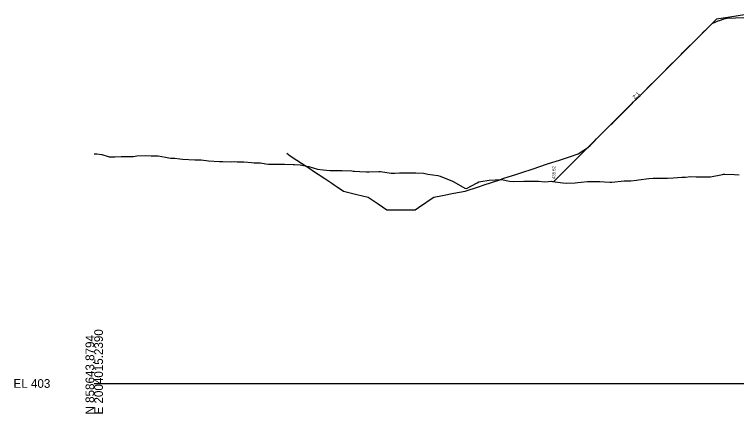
# Model space of a CAD drawing. Extents: x 2004049 to 2067449, y 841632 to 859611.
# Drawn here: x 2060920.8 to 2061153.3, y 856953.8 to 857082.4 of the extents above; entities that cross this region are included whole.
import ezdxf

# ---------------------------------------------------------------- set-up
doc = ezdxf.new("R2010")
doc.units = 0
for name, color, linetype in [('RD_DDB_Profile_Elev', 7, 'Continuous'), ('RD_GPK_XS_Cell', 7, 'Continuous'), ('RD_XS_EarthShd', 7, 'Continuous'), ('RD_XS_EwShp1', 7, 'Continuous'), ('RD_XS_ExGround', 7, 'Continuous'), ('RD_XS_TieSlope', 7, 'Continuous'), ('RD_XS_TX_Ditch', 7, 'Continuous'), ('RD_XS_TX_Slope', 7, 'Continuous')]:
    doc.layers.add(name, color=color, linetype=linetype)

msp = doc.modelspace()

# ---------------------------------------------------------------- linework, layer by layer
at = {"layer": 'RD_DDB_Profile_Elev'}
msp.add_lwpolyline([(2061008.46, 857037.69), (2061009.62, 857036.92), (2061011.71, 857035.53), (2061014.71, 857033.53), (2061015.22, 857033.19), (2061017.72, 857031.53), (2061018.59, 857030.95), (2061020.72, 857029.53), (2061022.95, 857028.04), (2061023.72, 857027.53), (2061024.34, 857027.12), (2061026.72, 857025.53), (2061031.03, 857024.45), (2061034.72, 857023.53), (2061037.92, 857021.39), (2061040.72, 857019.53), (2061044, 857019.53), (2061049.76, 857019.53), (2061051.91, 857020.95), (2061052.77, 857021.53), (2061054, 857022.34), (2061055.78, 857023.53), (2061058.58, 857024.08), (2061062.3, 857024.82), (2061064.09, 857025.17), (2061065.89, 857025.53), (2061070.16, 857026.93), (2061071.97, 857027.53), (2061077.07, 857029.2), (2061078.06, 857029.53), (2061082.53, 857031), (2061084.15, 857031.53), (2061087.44, 857032.61), (2061090.24, 857033.53), (2061090.58, 857033.64), (2061091.48, 857033.94), (2061092.13, 857034.16), (2061092.74, 857034.36), (2061096.27, 857035.53), (2061099.79, 857036.69), (2061102.33, 857037.53), (2061104.09, 857038.7), (2061104.92, 857039.22), (2061105.4, 857039.53), (2061106.1, 857040.22), (2061107.4, 857041.53), (2061108.22, 857042.34), (2061109.4, 857043.53), (2061110.68, 857044.81), (2061111.4, 857045.53), (2061112.84, 857046.96), (2061113.4, 857047.53), (2061115.44, 857049.56), (2061117.4, 857051.53), (2061118.12, 857052.25), (2061119.4, 857053.53), (2061120.14, 857054.27), (2061121.4, 857055.53), (2061122.24, 857056.37), (2061123.4, 857057.53), (2061125.4, 857059.53), (2061126.93, 857061.05), (2061127.4, 857061.53), (2061129.48, 857063.6), (2061131.4, 857065.53), (2061132.16, 857066.28), (2061133.4, 857067.53), (2061135.4, 857069.53), (2061135.89, 857070.02), (2061137.4, 857071.53), (2061139.51, 857073.64), (2061141.4, 857075.53), (2061142.89, 857077.02), (2061143.4, 857077.53), (2061144, 857078.13), (2061145.39, 857079.53), (2061147.31, 857080.33), (2061147.78, 857080.49), (2061149.31, 857081.06), (2061150.21, 857081.21), (2061155.61, 857081.42)], dxfattribs=at)
at = {"layer": 'RD_GPK_XS_Cell'}
msp.add_line((2060946.51, 856963.53), (2061196.51, 856963.53), dxfattribs=at)
at = {"layer": 'RD_XS_EarthShd'}
msp.add_line((2061156.51, 857082.45), (2061150.51, 857081.49), dxfattribs=at)
at = {"layer": 'RD_XS_EwShp1'}
for p, q in [((2061156.51, 857082.45), (2061150.51, 857081.49)), ((2061146.76, 857080.89), (2061094.45, 857028.57)), ((2061150.51, 857081.49), (2061146.76, 857080.89))]:
    msp.add_line(p, q, dxfattribs=at)
at = {"layer": 'RD_XS_ExGround'}
msp.add_lwpolyline([(2060946.51, 857037.57), (2060947.32, 857037.48), (2060949, 857037.34), (2060950.96, 857036.64), (2060951.27, 857036.57), (2060953.12, 857036.59), (2060955.22, 857036.62), (2060955.57, 857036.62), (2060959.17, 857036.68), (2060959.64, 857036.76), (2060960.19, 857036.85), (2060963.11, 857036.99), (2060964.8, 857036.89), (2060966.02, 857036.86), (2060967.06, 857036.89), (2060969.42, 857036.42), (2060971.01, 857036.15), (2060972.41, 857036.14), (2060974.04, 857035.91), (2060974.96, 857035.83), (2060978.91, 857035.62), (2060980.92, 857035.61), (2060983.27, 857035.3), (2060986.81, 857035.06), (2060987.89, 857035.05), (2060990.75, 857035), (2060991.56, 857035.02), (2060992.5, 857034.96), (2060994.7, 857034.91), (2060997.12, 857034.7), (2060997.94, 857034.62), (2060998.65, 857034.64), (2061000.07, 857034.68), (2061001.73, 857034.31), (2061002.6, 857034.21), (2061006.55, 857034.18), (2061007.72, 857034.16), (2061010.5, 857034.07), (2061010.97, 857034.08), (2061012.84, 857033.93), (2061014.44, 857033.7), (2061014.97, 857033.58), (2061015.58, 857033.41), (2061018.39, 857032.6), (2061020.2, 857032.34), (2061022.34, 857032.19), (2061023.48, 857032.15), (2061024.81, 857032.15), (2061026.29, 857032.17), (2061029.43, 857032), (2061029.87, 857031.99), (2061030.24, 857031.95), (2061031.99, 857031.84), (2061034.19, 857031.68), (2061035.01, 857031.72), (2061038.14, 857031.85), (2061038.66, 857031.8), (2061042.08, 857031.35), (2061043.28, 857031.34), (2061044.76, 857031.42), (2061046.03, 857031.38), (2061046.89, 857031.43), (2061047.9, 857031.42), (2061049.98, 857031.39), (2061052.51, 857031.26), (2061053.93, 857031.01), (2061057.13, 857030.51), (2061057.88, 857030.28), (2061061.83, 857028.76), (2061062.31, 857028.5), (2061065.77, 857026.51), (2061066.36, 857026.4), (2061069.72, 857028.16), (2061070.3, 857028.48), (2061070.98, 857028.63), (2061073.67, 857029.01), (2061075.59, 857029.15), (2061077.62, 857029.23), (2061080.21, 857028.74), (2061081.57, 857028.56), (2061084.83, 857028.72), (2061085.52, 857028.68), (2061089.46, 857028.75), (2061091.58, 857028.51), (2061093.71, 857028.68), (2061094.06, 857028.63), (2061097.36, 857028.14), (2061098.67, 857028.09), (2061101.31, 857028.13), (2061102.22, 857028.25), (2061103.29, 857028.43), (2061105.26, 857028.63), (2061107.91, 857028.64), (2061108.61, 857028.63), (2061109.21, 857028.59), (2061110.74, 857028.49), (2061112.52, 857028.4), (2061113.16, 857028.42), (2061117.14, 857028.88), (2061119.25, 857028.79), (2061121.05, 857029.02), (2061121.75, 857029.12), (2061125, 857029.58), (2061126.37, 857029.67), (2061128.95, 857029.65), (2061129.89, 857029.65), (2061130.99, 857029.68), (2061132.9, 857029.75), (2061135.6, 857029.97), (2061136.85, 857030.05), (2061138.4, 857030.18), (2061140.22, 857030.11), (2061140.79, 857030.12), (2061144.2, 857030.15), (2061144.84, 857030.17), (2061148.69, 857030.88), (2061149.04, 857030.93), (2061149.45, 857030.97), (2061152.64, 857030.92), (2061154.07, 857030.72)], dxfattribs=at)
at = {"layer": 'RD_XS_TieSlope'}
for p, q in [((2061146.76, 857080.89), (2061094.45, 857028.57)), ((2061150.51, 857081.49), (2061146.76, 857080.89))]:
    msp.add_line(p, q, dxfattribs=at)

# ---------------------------------------------------------------- texts
at = {"layer": 'RD_GPK_XS_Cell'}
for s, p in [('E 2004015.2390', (2060949.31, 856953.53)), ('N 858643.8794', (2060946.51, 856953.53))]:
    msp.add_text(s, height=2.8, rotation=90, dxfattribs=at).set_placement(p)
msp.add_text('EL 403', height=2.8, dxfattribs=at).set_placement((2060920.51, 856962.13))
at = {"layer": 'RD_XS_TX_Ditch'}
msp.add_text('435.52', height=1, rotation=90, dxfattribs=at).set_placement((2061094.95, 857029.37))
at = {"layer": 'RD_XS_TX_Slope'}
msp.add_text('2:1', height=1.25, rotation=45, dxfattribs=at).set_placement((2061120.52, 857055.09))

doc.saveas('drawing.dxf')
